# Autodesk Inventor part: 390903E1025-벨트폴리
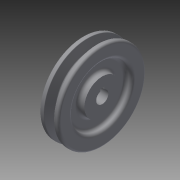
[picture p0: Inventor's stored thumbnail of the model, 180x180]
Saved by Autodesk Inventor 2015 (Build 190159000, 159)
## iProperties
Created: 2019-09
Part Number: 390903E1025-벨트폴리
Material: 일반
Document SubType Name: Modeling
Designer: now
Density: 1 g/cm^3
Appearance: 기본값
Mass: 73.3597 g
Surface Area: 224.091 cm^2
Volume: 73.3597 cm^3
Author: now
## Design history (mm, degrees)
sketch "스케치1"
  geometry: C1 r 42.7 at (0, 0); 1 further point
  constraints: 1 centre point, 1 coincident
  dimensions: "d0" = 85.4 diameter of C1
extrude "돌출1" new body sketch "스케치1" stored distance "d1" = 19; taper "d2" = 0 deg
sketch "스케치2"
  geometry: C1 r 42.7 at (0, 0) reference; C2 r 17.5 at (0, 0)
  constraints: 1 centre point, 1 coincident
  dimensions: "d3" = 35 diameter of C2
extrude "돌출2" join sketch "스케치2" distance "d4" = 5; taper "d5" = 0 deg
sketch "스케치3"
  geometry: L1 (9.5, 17.5)-(14.5, 17.5) reference; L2 (14.5, 17.5)-(14.5, -17.5) reference; L3 (14.5, -17.5)-(9.5, -17.5) reference; L4 (9.5, -17.5)-(9.5, -42.7) reference; L5 (9.5, -42.7)-(-9.5, -42.7) reference; L6 (-9.5, -42.7)-(-9.5, 42.7) reference; L7 (-9.5, 42.7)-(9.5, 42.7) reference; L8 (9.5, 42.7)-(9.5, 17.5) reference; L9 (4.877, 42.7)-(1.953, 33.7); L10 (1.953, 33.7)-(-1.953, 33.7); L11 (-1.953, 33.7)-(-4.877, 42.7); L12 (0, 42.7)-(0, 33.7); L13 (4, 40)-(-4, 40); L14 (19.3, 0)-(-14.3, 0) reference; 1 further point
  constraints: 10 end point, 4 point on line, 2 horizontal, 2 midpoint, 1 vertical, 1 other
  dimensions: "d30" = 36 deg angle of L11 L9; "d31" = 2.7 distance between parallel lines of L13 L7; "d32" = 6.3 distance between parallel lines of L10 L13; "d33" = 8 distance of L13.start L13.end
revolve "회전1" sketch "스케치3" stored, may be unused: angle "d10" = 90 deg
sketch "스케치4"
  geometry: C1 r 42.7 at (0, 0) reference
hole "구멍1" sketch "스케치4" at (0, 0) diameter "d11" = 12; stored, may be unused: countersink angle "d15" = 90 deg, drill point angle "d17" = 118 deg; dims "d12" = 6, "d13" = 4, "d14" = 2, "d16" = 8
sketch "스케치5"
  geometry: L1 (-7.8, -2)-(0, -2); L2 (0, -2)-(0, 2); L3 (0, 2)-(-7.8, 2); L4 (-7.8, 2)-(-7.8, -2); C1 r 6 at (0, 0) reference; 1 further point
  constraints: 8 end point, 2 coincident, 2 parallel, 1 horizontal, 1 midpoint, 1 perpendicular
  dimensions: "d18" = 4 distance of L3.end L1.start; "d19" = 7.8 distance from line of C1.centre L4
extrude "돌출3" cut sketch "스케치5" distance "d20" = 25; taper "d21" = 0 deg
sketch "스케치6"
  geometry: C1 r 17.5 at (0, 0) reference; C2 r 42.7 at (0, 0) reference; C3 r 29 at (0, 0); C4 r 17.5 at (0, 0)
  constraints: 2 centre point, 2 coincident
  dimensions: "d22" = 58 diameter of C3; "d23" = 35 diameter of C4
extrude "돌출4" cut sketch "스케치6" distance "d24" = 6; taper "d25" = 0 deg
fillet "모깎기1" dims "d26" = 1
fillet "모깎기2" dims "d27" = 0.5
fillet "모깎기3" dims "d28" = 2
fillet "모깎기4" dims "d29" = 3
node "솔리드1"
mirror "대칭1"
node "절단 모서리 투영1"
